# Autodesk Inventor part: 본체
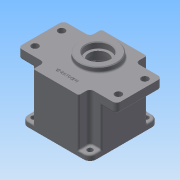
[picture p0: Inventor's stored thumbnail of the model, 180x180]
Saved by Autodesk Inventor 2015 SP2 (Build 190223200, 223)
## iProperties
Created: 2015-06
Part Number: 본체
Material: 일반
Document SubType Name: Modeling
Designer: AMC
Density: 1 g/cm^3
Appearance: 기본값
Author: AMC
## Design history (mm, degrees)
sketch "스케치1"
  geometry: L1 (65, 30)-(65, -30); L2 (-65, -30)-(-65, 30); L3 (30, -45)-(-30, -45); L4 (-30, 45)-(30, 45); L5 (-65, 30)-(-30, 30); L6 (30, 30)-(65, 30); L7 (65, -30)-(30, -30); L8 (-30, -30)-(-65, -30); L9 (30, 45)-(30, 30); L10 (30, -30)-(30, -45); L11 (-30, -45)-(-30, -30); L12 (-30, 30)-(-30, 45); 3 further points
  constraints: 24 end point, 10 parallel, 4 perpendicular, 3 horizontal, 3 horizontal alignment, 3 vertical alignment, 2 collinear, 2 midpoint
  dimensions: "d0" = 60 distance of L4.start L4.end; "d1" = 60 distance of L1.start L1.end; "d2" = 130 distance between parallel lines of L1 L2; "d3" = 90 distance between parallel lines of L3 L4
extrude "돌출1" new body sketch "스케치1" distance "d4" = 12; taper "d5" = 0 deg
sketch "스케치2"
  geometry: L1 (-45, 45)-(45, 45); L2 (45, 45)-(45, -45); L3 (45, -45)-(-45, -45); L4 (-45, -45)-(-45, 45); L5 (-30, 45)-(30, 45) reference; 2 further points
  constraints: 8 end point, 2 midpoint, 2 parallel, 2 perpendicular, 1 horizontal
  dimensions: "d6" = 90 distance of L1.start L1.end
extrude "돌출2" join sketch "스케치2" distance "d7" = 58; taper "d8" = 0 deg
sketch "스케치3"
  geometry: L1 (45, 45)-(30, 45); L2 (30, 45)-(30, 30); L3 (30, 30)-(45, 30); L4 (45, 30)-(45, 45); 1 further point
  constraints: 8 end point, 2 parallel, 1 horizontal, 1 perpendicular
extrude "돌출3" cut sketch "스케치3" distance "d9" = 51; taper "d10" = 0 deg
fillet "모깎기1" dims "d11" = 8
hole "구멍1" diameter "d14" = 7; stored, may be unused: countersink angle "d18" = 90 deg, drill point angle "d20" = 118 deg; dims "d12" = 10, "d13" = 10, "d15" = 6, "d16" = 4, "d17" = 2, "d19" = 8
fillet "모깎기2" dims "d21" = 5
fillet "모깎기3" dims "d22" = 5
fillet "모깎기4" dims "d23" = 8
fillet "모깎기5" dims "d24" = 2
fillet "모깎기6" dims "d25" = 2
fillet "모깎기7" dims "d26" = 5
sketch "스케치4"
  geometry: 3 further points
  constraints: 1 vertical alignment
  dimensions: "d27" = 35 distance of point (-55, -17.5) point (-55, 17.5); "d28" = 17.5 vertical distance of point (0, 0) point (-55, 17.5); "d29" = 55 horizontal distance of point (0, 0) point (-55, 17.5)
hole "구멍2" sketch "스케치4" at (-55, 17.5), (-55, -17.5) diameter "d30" = 9; stored, may be unused: countersink angle "d34" = 90 deg, drill point angle "d36" = 118 deg; dims "d31" = 6, "d32" = 4, "d33" = 2, "d35" = 8
fillet "모깎기8" dims "d37" = 2
sketch "스케치5"
  geometry: C1 r 25 at (0, 11); 1 further point
  constraints: 1 centre point, 1 vertical alignment
  dimensions: "d38" = 50 diameter of C1; "d39" = 11 distance of point (0, 0) C1.centre
extrude "돌출4" join sketch "스케치5" distance "d40" = 7; taper "d41" = 0 deg
sketch "스케치6"
  geometry: 1 further point
hole "구멍3" sketch "스케치6" at (0, 0) diameter "d42" = 78; stored, may be unused: countersink angle "d46" = 90 deg, drill point angle "d48" = 0 deg; dims "d43" = 6, "d44" = 80, "d45" = 9, "d47" = 61
sketch "스케치7"
  geometry: L1 (0, 0)-(30.77, 30.77); L2 (0, 0)-(43.515, 0); L3 (24.603, 30.26)-(21.758, 27.415); L4 (30.26, 24.603)-(27.415, 21.758); A1 r 35 centre (0, 0) between (24.749, 24.749) and (27.415, 21.758); A2 r 4 centre (24.749, 24.749) between (21.92, 27.577) and (27.577, 21.92); A3 r 39 centre (0, 0) between (30.26, 24.603) and (24.603, 30.26); 1 further point
  constraints: 8 end point, 7 point on circle, 3 centre point, 3 point on line, 2 coincident, 2 tangent, 1 equal length, 1 horizontal
  dimensions: "d49" = 70 diameter of A1; "d50" = 45 deg angle of L2 L1; "d52" = 78 diameter of A3; "d53" = 8 diameter of A2
extrude "돌출5" join sketch "스케치7" stored distance "d55" = 7; taper "d56" = 0 deg
fillet "모깎기9" dims "d57" = 3.5
fillet "모깎기10" dims "d61" = 2
hole "구멍4" diameter "d64" = 3.459; stored, may be unused: countersink angle "d68" = 90 deg, drill point angle "d70" = 118 deg; dims "d65" = 12, "d66" = 80, "d67" = 9, "d69" = 15, "d153" = 10, "d154" = 10
sketch "스케치10"
  geometry: A1 r 20.5 centre (0, 11) between (7.402, -8.117) and (-7.402, -8.117); A2 r 14 centre (0, -20) between (-7.402, -8.117) and (7.402, -8.117); 1 further point
  constraints: 4 point on circle, 2 centre point, 2 vertical alignment
  dimensions: "d105" = 41 diameter of A1; "d106" = 11 distance of point (0, 0) A1.centre; "d107" = 28 diameter of A2; "d108" = 20 distance of point (0, 0) A2.centre
extrude "돌출8" join sketch "스케치10" distance "d109" = 7; taper "d110" = 0 deg
fillet "모깎기13" dims "d111" = 3
fillet "모깎기14" dims "d112" = 2
hole "구멍7" diameter "d115" = 35; stored, may be unused: countersink angle "d119" = 90 deg, drill point angle "d121" = 0 deg; dims "d113" = 10, "d114" = 10, "d116" = 6, "d117" = 32, "d118" = 8, "d120" = 10
hole "구멍8" diameter "d124" = 25; stored, may be unused: countersink angle "d128" = 90 deg, drill point angle "d130" = 0 deg; dims "d122" = 10, "d123" = 10, "d125" = 6, "d126" = 32, "d127" = 8, "d129" = 10
fillet "모깎기15" dims "d131" = 0.3
fillet "모깎기16" dims "d132" = 2
chamfer "모따기2" distance "d133" = 1; stored, may be unused: second distance "d134" = 2, angle "d135" = 45 deg
hole "구멍9" diameter "d138" = 19; stored, may be unused: countersink angle "d142" = 90 deg, drill point angle "d144" = 0 deg; dims "d136" = 10, "d137" = 10, "d139" = 6, "d140" = 22, "d141" = 7, "d143" = 8
fillet "모깎기17" dims "d145" = 2
fillet "모깎기18" dims "d146" = 0.3
chamfer "모따기3" distance "d147" = 1; stored, may be unused: second distance "d148" = 2, angle "d149" = 45 deg
sketch "스케치11"
  geometry: L1 (-28, -45)-(28, -45) reference; 3 further points
  constraints: 1 midpoint, 1 vertical alignment, 1 other
  dimensions: "d150" = 15 distance of point (0, -45) point (0, -30)
extrude "돌출9" join sketch "스케치11" distance "d151" = 0.5; taper "d152" = 0 deg
node "솔리드1"
mirror "대칭1"
mirror "대칭2"
mirror "대칭3"
pattern_circular "원형 패턴1" dims angle "d59" = 360 deg
pattern_circular "원형 패턴2" dims angle "d72" = 360 deg
